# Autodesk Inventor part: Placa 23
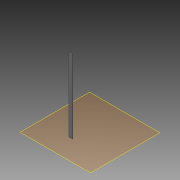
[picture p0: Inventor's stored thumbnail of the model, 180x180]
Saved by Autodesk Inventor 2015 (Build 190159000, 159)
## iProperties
Created: 2015-04
Part Number: Placa 23
Material: Generic
Document SubType Name: Modeling
Designer: suporte
Density: 1 g/cm^3
Appearance: Default
Author: suporte
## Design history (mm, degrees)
workplane "Work Plane1"
sketch "Sketch1"
  geometry: L1 (-87.5, -412.5)-(-87.5, -400) reference; L2 (-87.5, -412.5)-(-187.5, -412.5); L3 (-187.5, -412.5)-(-187.5, -400); L4 (-187.5, -400)-(-87.5, -400); L5 (-87.5, -400)-(-87.5, -412.5); 1 further point
  constraints: 8 end point, 2 parallel, 1 horizontal, 1 perpendicular
extrude "Extrusion1" new body sketch "Sketch1" distance "d0" = 2100; taper "d1" = 0 deg
body "Solid1"
node "Reference1"
node "Reference2"
